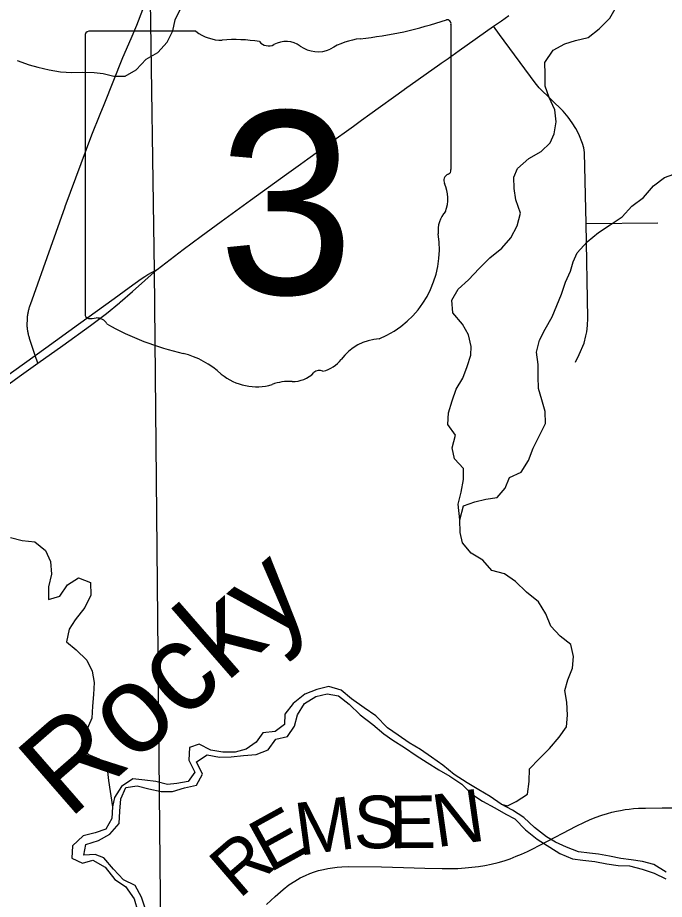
# Model space of a CAD drawing. Extents: x 0 to 34, y 0 to 22.
# Drawn here: x 6.6481 to 6.9977, y 17.3987 to 17.8754 of the extents above; entities that cross this region are included whole.
import ezdxf

# ---------------------------------------------------------------- set-up
doc = ezdxf.new("R2010")
doc.units = 0
for name, color, linetype in [('GM_X_County_Road', 7, 'Continuous'), ('GM_X_County_Road_Text', 7, 'Continuous'), ('GM_X_Minor_River', 7, 'Continuous'), ('GM_X_Minor_River_Text', 7, 'Continuous'), ('GM_X_Rail_Line_Text', 7, 'Continuous'), ('GM_X_State_Location', 7, 'Continuous'), ('GM_X_State_Route', 7, 'Continuous'), ('GM_X_State_Shield', 7, 'Continuous'), ('GM_X_Township', 7, 'Continuous'), ('GM_X_Township_Road', 7, 'Continuous')]:
    doc.layers.add(name, color=color, linetype=linetype)

msp = doc.modelspace()

# ---------------------------------------------------------------- linework, layer by layer
at = {"layer": 'GM_X_County_Road'}
for points in [[(6.659023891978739, 17.68859297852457), (6.657610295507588, 17.69283072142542), (6.654935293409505, 17.700846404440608), (6.654733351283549, 17.701418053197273), (6.654578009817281, 17.701887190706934), (6.654428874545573, 17.702359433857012), (6.654292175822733, 17.702834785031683), (6.654161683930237, 17.703310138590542), (6.654037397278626, 17.70379170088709), (6.653922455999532, 17.70427326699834), (6.653816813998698, 17.704754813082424), (6.653720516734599, 17.705239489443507), (6.65363351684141, 17.705727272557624), (6.653552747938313, 17.706215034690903), (6.653481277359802, 17.70670282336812), (6.653416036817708, 17.70719369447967), (6.653363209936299, 17.707684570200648), (6.653316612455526, 17.708178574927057), (6.653279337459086, 17.708672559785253), (6.6533507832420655, 17.71305942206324), (6.65340049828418, 17.71355962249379), (6.653459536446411, 17.71405672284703), (6.653527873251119, 17.714553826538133), (6.653605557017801, 17.715047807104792), (6.653692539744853, 17.715541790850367), (6.653785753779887, 17.716032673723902), (6.653888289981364, 17.716523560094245), (6.654000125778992, 17.717011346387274), (6.654121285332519, 17.717496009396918), (6.6542486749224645, 17.717980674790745), (6.654385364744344, 17.718462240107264), (6.654531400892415, 17.718940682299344), (6.654683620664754, 17.719419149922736), (6.654845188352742, 17.71989139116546), (6.655016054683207, 17.720363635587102), (6.666032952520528, 17.75132339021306), (6.6737876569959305, 17.773114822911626), (6.673828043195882, 17.773226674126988), (6.688278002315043, 17.812068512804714), (6.692680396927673, 17.823153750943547), (6.694780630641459, 17.828444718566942), (6.704896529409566, 17.853920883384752), (6.709392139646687, 17.8640243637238), (6.712558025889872, 17.87132234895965), (6.71577050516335, 17.87972016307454)], [(6.782536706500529, 17.3958811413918), (6.787274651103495, 17.400373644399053), (6.791562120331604, 17.40412360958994), (6.794774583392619, 17.40651278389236), (6.797865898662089, 17.40857572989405), (6.80083295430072, 17.41030623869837), (6.8037161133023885, 17.411707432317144), (6.806108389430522, 17.41269539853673), (6.8086218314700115, 17.41360260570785), (6.810805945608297, 17.414301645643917), (6.813359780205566, 17.41496029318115), (6.815708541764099, 17.415457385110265), (6.818221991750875, 17.415827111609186), (6.820735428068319, 17.416116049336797), (6.823332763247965, 17.416321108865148), (6.827123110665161, 17.416445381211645), (6.844760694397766, 17.416280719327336), (6.856709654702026, 17.41599177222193), (6.868208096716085, 17.415538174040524), (6.877643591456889, 17.4153735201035), (6.886050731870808, 17.415497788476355), (6.8899653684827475, 17.41574322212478), (6.893591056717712, 17.416072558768), (6.897300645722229, 17.416526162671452), (6.900597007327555, 17.41702325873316), (6.904098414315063, 17.417722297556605), (6.9077676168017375, 17.418629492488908), (6.911104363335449, 17.419577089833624), (6.914319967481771, 17.42068934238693), (6.917656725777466, 17.422006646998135), (6.92049949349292, 17.42324315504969), (6.923618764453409, 17.42465368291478), (6.92664172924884, 17.426113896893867), (6.929962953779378, 17.4278071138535), (6.934592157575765, 17.43016833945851), (6.9427942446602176, 17.43461733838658), (6.950045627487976, 17.438367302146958), (6.954497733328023, 17.44054831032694), (6.957154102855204, 17.441750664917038), (6.960319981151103, 17.442987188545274), (6.963858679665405, 17.44425788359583), (6.966859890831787, 17.445208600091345), (6.96932983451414, 17.44586724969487), (6.971802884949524, 17.44644511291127), (6.973987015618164, 17.446855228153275), (6.976460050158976, 17.447268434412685), (6.978684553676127, 17.44755736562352), (6.981073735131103, 17.447802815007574), (6.983711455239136, 17.448010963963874), (6.987545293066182, 17.448091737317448), (6.996527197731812, 17.448175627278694), (7.005387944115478, 17.448216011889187)]]:
    msp.add_lwpolyline(points, dxfattribs=at)
at = {"layer": 'GM_X_Minor_River'}
for points in [[(6.647802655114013, 17.852279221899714), (6.654275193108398, 17.8499260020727), (6.659026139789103, 17.848680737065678), (6.665106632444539, 17.847079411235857), (6.671176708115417, 17.846048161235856), (6.677422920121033, 17.845778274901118), (6.683095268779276, 17.845876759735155), (6.689527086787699, 17.84580005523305), (6.694267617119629, 17.845123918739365), (6.700155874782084, 17.84370914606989), (6.706206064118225, 17.843814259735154), (6.712199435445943, 17.847144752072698), (6.717582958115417, 17.85293073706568), (6.7239513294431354, 17.85645630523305), (6.7289598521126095, 17.862046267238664), (6.732066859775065, 17.86817126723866), (6.733284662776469, 17.874263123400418), (6.7365734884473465, 17.880770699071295)], [(6.887083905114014, 17.603966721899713), (6.8861804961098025, 17.612298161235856), (6.887769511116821, 17.61877448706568), (6.889160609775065, 17.625628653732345), (6.889054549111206, 17.63169778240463), (6.884233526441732, 17.636924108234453), (6.882995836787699, 17.64278395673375), (6.884765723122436, 17.649643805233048), (6.880691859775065, 17.655452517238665), (6.88095985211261, 17.661717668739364), (6.882926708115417, 17.668201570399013), (6.885083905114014, 17.67449986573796), (6.8887628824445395, 17.680444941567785), (6.8911104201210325, 17.686746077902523), (6.893082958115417, 17.69285024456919), (6.893189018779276, 17.697595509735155), (6.89175530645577, 17.703830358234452), (6.888626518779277, 17.70965611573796), (6.883410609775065, 17.71582467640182), (6.882723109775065, 17.722641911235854), (6.886212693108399, 17.72858509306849), (6.891797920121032, 17.733614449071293), (6.897552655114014, 17.739784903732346), (6.90331307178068, 17.74557751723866), (6.909840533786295, 17.750814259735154), (6.914660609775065, 17.75639948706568), (6.918138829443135, 17.762909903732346), (6.919909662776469, 17.769770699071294), (6.917324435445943, 17.77693452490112), (6.9164607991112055, 17.782989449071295), (6.916354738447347, 17.78905952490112), (6.918350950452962, 17.793836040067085), (6.924496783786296, 17.799255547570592), (6.931050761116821, 17.80297524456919), (6.935886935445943, 17.80761255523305), (6.938068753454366, 17.812583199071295), (6.939278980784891, 17.819053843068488), (6.938408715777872, 17.825489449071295), (6.935453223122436, 17.832266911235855), (6.933265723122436, 17.83830005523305), (6.933341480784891, 17.844751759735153), (6.933039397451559, 17.851196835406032), (6.9376520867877, 17.857727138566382), (6.943832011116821, 17.861250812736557), (6.949663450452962, 17.863060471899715), (6.95644280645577, 17.86469588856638), (6.962413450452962, 17.869353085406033), (6.968174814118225, 17.875145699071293), (6.971846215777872, 17.881470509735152)], [(6.887083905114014, 17.603966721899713), (6.889033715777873, 17.611398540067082), (6.895236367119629, 17.61359456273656), (6.90126288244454, 17.615028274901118), (6.907300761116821, 17.615891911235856), (6.911559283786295, 17.621088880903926), (6.913917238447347, 17.62682088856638), (6.920298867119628, 17.62958793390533), (6.924158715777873, 17.635915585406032), (6.9266890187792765, 17.642598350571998), (6.9301615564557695, 17.649489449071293), (6.933450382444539, 17.655996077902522), (6.933337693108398, 17.662443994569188), (6.9315223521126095, 17.668862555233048), (6.929713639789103, 17.67490043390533), (6.929410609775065, 17.681345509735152), (6.929486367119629, 17.687796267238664), (6.928609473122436, 17.69460971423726), (6.93019754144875, 17.70108793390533), (6.933308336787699, 17.707023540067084), (6.936973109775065, 17.71372713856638), (6.94205360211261, 17.725956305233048), (6.944208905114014, 17.732443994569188), (6.946941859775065, 17.738372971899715), (6.948367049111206, 17.743330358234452), (6.950548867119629, 17.74830005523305), (6.95592860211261, 17.75427543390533), (6.962081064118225, 17.75931520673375), (6.968439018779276, 17.763410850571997), (6.974795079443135, 17.767694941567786), (6.980177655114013, 17.77348092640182), (6.986337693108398, 17.77814096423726), (6.991899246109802, 17.784498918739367), (6.997684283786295, 17.788963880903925), (7.0027590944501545, 17.790759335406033)], [(6.909466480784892, 17.450140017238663), (6.912872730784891, 17.449371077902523), (6.917574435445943, 17.45160971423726), (6.9237429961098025, 17.455700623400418), (6.924567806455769, 17.462544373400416), (6.924825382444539, 17.46937770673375), (6.930026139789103, 17.474780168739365), (6.9356018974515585, 17.480378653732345), (6.940792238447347, 17.486349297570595), (6.944854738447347, 17.49192221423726), (6.945307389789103, 17.498379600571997), (6.944994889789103, 17.505391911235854), (6.943939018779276, 17.51163338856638), (6.945541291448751, 17.51735213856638), (6.948077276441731, 17.52365611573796), (6.948530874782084, 17.530113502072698), (6.947093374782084, 17.536538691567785), (6.941341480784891, 17.54099039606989), (6.936329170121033, 17.54640327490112), (6.933561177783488, 17.553183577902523), (6.929666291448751, 17.55956520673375), (6.923143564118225, 17.56476217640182), (6.917178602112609, 17.57053774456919), (6.9112411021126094, 17.574798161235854), (6.9044001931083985, 17.57657467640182), (6.899573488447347, 17.58218073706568), (6.893266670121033, 17.585864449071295), (6.888628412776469, 17.591474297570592), (6.887393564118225, 17.59714380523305), (6.887083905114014, 17.603966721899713)], [(6.644214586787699, 17.594405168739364), (6.650484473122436, 17.592807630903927), (6.657307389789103, 17.591978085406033), (6.663064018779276, 17.58733698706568), (6.665816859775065, 17.58131520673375), (6.666315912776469, 17.57449418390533), (6.6647344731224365, 17.56763717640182), (6.664855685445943, 17.560810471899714), (6.67087557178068, 17.562623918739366), (6.675117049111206, 17.568766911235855), (6.680915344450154, 17.572473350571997), (6.687386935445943, 17.570121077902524), (6.68770038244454, 17.56310782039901), (6.684409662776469, 17.55660024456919), (6.679233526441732, 17.549870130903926), (6.67591629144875, 17.544880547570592), (6.674524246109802, 17.538027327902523), (6.67970985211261, 17.533564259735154), (6.685482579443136, 17.527975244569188), (6.688421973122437, 17.522145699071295), (6.689477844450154, 17.515904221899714), (6.689024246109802, 17.50944683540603), (6.688566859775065, 17.503178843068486), (6.688113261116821, 17.49672145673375), (6.685212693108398, 17.489651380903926), (6.682496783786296, 17.48277543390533), (6.6860005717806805, 17.477145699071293), (6.691905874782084, 17.474783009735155), (6.6965375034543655, 17.469552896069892), (6.697221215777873, 17.4629260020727), (6.6993632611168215, 17.448735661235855)], [(6.99863030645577, 17.413384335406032), (6.991936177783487, 17.417630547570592), (6.985854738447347, 17.41923092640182), (6.979787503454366, 17.420072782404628), (6.97409905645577, 17.420921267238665), (6.9680251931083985, 17.42214285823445), (6.962143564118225, 17.42317789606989), (6.957217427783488, 17.423660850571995), (6.951338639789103, 17.42450649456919), (6.944864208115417, 17.427049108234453), (6.938766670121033, 17.429597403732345), (6.933986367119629, 17.43254910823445), (6.927467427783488, 17.43755573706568), (6.921697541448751, 17.442956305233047), (6.915573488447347, 17.447022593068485), (6.909466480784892, 17.450140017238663), (6.903528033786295, 17.454398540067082), (6.897414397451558, 17.457895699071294), (6.891104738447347, 17.46176880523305), (6.884028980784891, 17.46619683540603), (6.877887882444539, 17.471211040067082), (6.871757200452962, 17.475656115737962), (6.865821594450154, 17.479725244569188), (6.859705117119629, 17.483411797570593), (6.8537695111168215, 17.487481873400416), (6.8480232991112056, 17.491554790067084), (6.841671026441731, 17.49789285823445), (6.835350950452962, 17.50233414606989), (6.828646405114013, 17.50714948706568), (6.822890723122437, 17.511790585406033), (6.816235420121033, 17.513761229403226), (6.809833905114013, 17.51213149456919), (6.803256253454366, 17.509739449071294), (6.797104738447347, 17.504700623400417), (6.792477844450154, 17.49892789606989), (6.792388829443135, 17.493235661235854), (6.787347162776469, 17.489544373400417), (6.780549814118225, 17.488854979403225), (6.777047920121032, 17.483673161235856), (6.771629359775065, 17.479973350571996), (6.7656047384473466, 17.47835024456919), (6.758987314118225, 17.478233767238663), (6.752535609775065, 17.47944967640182), (6.746239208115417, 17.482564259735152), (6.740975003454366, 17.480765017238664), (6.740717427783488, 17.47393073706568), (6.7438566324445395, 17.467535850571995), (6.740350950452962, 17.46254342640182), (6.734131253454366, 17.461296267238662), (6.72903182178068, 17.460826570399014), (6.722762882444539, 17.462425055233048), (6.716885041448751, 17.463269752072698), (6.710442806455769, 17.46391558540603), (6.704274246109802, 17.45982467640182), (6.70040682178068, 17.453876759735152), (6.6993632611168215, 17.448735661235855), (6.699095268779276, 17.44247145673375), (6.695792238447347, 17.436722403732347), (6.689963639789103, 17.434723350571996), (6.6835621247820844, 17.433094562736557), (6.677794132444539, 17.42768168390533), (6.67734432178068, 17.42103395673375), (6.683066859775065, 17.41828963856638), (6.688712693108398, 17.419906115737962), (6.695396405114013, 17.41622903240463), (6.700621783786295, 17.40949229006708), (6.706365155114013, 17.405609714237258), (6.711019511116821, 17.3990510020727), (6.713030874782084, 17.392257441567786)], [(6.717170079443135, 17.393467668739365), (6.7149768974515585, 17.399879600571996), (6.711649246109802, 17.406270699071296), (6.705351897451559, 17.409385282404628), (6.699957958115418, 17.414981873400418), (6.6947420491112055, 17.42114948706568), (6.689981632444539, 17.42296293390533), (6.683935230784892, 17.422667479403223), (6.68496932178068, 17.428376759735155), (6.6917392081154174, 17.430581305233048), (6.697921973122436, 17.43391558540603), (6.702926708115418, 17.439693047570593), (6.703376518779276, 17.446340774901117), (6.703823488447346, 17.453176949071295), (6.706552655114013, 17.45929532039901), (6.712778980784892, 17.46016274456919), (6.7190488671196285, 17.458566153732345), (6.725696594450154, 17.456974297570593), (6.731746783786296, 17.457080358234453), (6.738331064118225, 17.459092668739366), (6.7447363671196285, 17.46053395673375), (6.748035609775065, 17.46647145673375), (6.744704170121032, 17.47305289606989), (6.7504986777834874, 17.476946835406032), (6.757143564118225, 17.475546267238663), (6.76356780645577, 17.475848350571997), (6.770176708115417, 17.476533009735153), (6.776975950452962, 17.47703206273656), (6.783549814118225, 17.479612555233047), (6.787610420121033, 17.48537486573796), (6.794014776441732, 17.48681520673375), (6.797700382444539, 17.492380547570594), (6.7992941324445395, 17.498479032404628), (6.803158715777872, 17.504616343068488), (6.809333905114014, 17.50832846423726), (6.815361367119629, 17.50976217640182), (6.821620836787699, 17.50873282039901), (6.827373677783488, 17.50428111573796), (6.8333376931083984, 17.49850554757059), (6.840049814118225, 17.49331236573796), (6.846001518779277, 17.488294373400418), (6.850980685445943, 17.484777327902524), (6.8572903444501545, 17.480904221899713), (6.863609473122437, 17.47646198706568), (6.869538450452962, 17.472772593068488), (6.875850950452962, 17.468710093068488), (6.88177235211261, 17.465399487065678), (6.888282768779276, 17.460960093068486), (6.893672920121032, 17.455553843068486), (6.899412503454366, 17.451860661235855), (6.906097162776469, 17.448183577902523), (6.912018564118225, 17.444872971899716), (6.916792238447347, 17.4423010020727), (6.9225715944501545, 17.4363322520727), (6.928901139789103, 17.43132183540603), (6.941142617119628, 17.423568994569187), (6.948003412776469, 17.420654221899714), (6.953688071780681, 17.419995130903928), (6.960133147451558, 17.419159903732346), (6.966585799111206, 17.41794399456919), (6.972653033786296, 17.41710213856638), (6.978899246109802, 17.416832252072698), (6.985739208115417, 17.41505573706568), (6.992208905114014, 17.412891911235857), (6.998504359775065, 17.409778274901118)]]:
    msp.add_lwpolyline(points, dxfattribs=at)
at = {"layer": 'GM_X_Rail_Line_Text'}
msp.add_lwpolyline([(7.255462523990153, 17.906184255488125), (6.967662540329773, 17.900846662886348), (6.9468000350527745, 17.9005173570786), (6.719611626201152, 17.89693202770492), (6.721941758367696, 17.738473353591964), (6.725763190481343, 17.34372005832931), (6.731116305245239, 16.7724510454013), (6.731100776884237, 16.538635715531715), (6.731114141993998, 16.53753691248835), (6.731609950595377, 16.496752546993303), (6.731638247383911, 16.49442522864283), (6.731696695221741, 16.480747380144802), (6.732387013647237, 16.319149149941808), (6.74000812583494, 15.641470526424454), (6.982830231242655, 15.643260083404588), (6.999225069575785, 15.643974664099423)], dxfattribs=at)
at = {"layer": 'GM_X_State_Route'}
for points in [[(6.880834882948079, 17.85337380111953), (6.8816669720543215, 17.853948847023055), (6.88282270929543, 17.854762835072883), (6.886787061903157, 17.857559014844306), (6.905235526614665, 17.870815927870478), (6.909609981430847, 17.87365558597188), (6.913591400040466, 17.876509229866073)], [(6.723546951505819, 17.739265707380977), (6.737530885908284, 17.750105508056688), (6.7472491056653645, 17.75732581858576), (6.758026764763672, 17.765155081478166), (6.774033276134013, 17.776780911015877), (6.793398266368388, 17.790715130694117), (6.801044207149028, 17.796217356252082), (6.804878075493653, 17.798976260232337), (6.816426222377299, 17.80728707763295), (6.829558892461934, 17.816738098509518), (6.834004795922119, 17.81993817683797), (6.83853767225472, 17.82320036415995), (6.857104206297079, 17.836559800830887), (6.857194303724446, 17.836625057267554), (6.87637912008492, 17.850292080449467), (6.877090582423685, 17.85078608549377), (6.880834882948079, 17.85337380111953)], [(6.597008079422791, 17.649325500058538), (6.604219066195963, 17.654560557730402), (6.626641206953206, 17.670514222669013), (6.640308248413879, 17.680362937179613), (6.657610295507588, 17.69283072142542), (6.663264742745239, 17.696903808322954), (6.680967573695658, 17.70968229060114), (6.7003294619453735, 17.723569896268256), (6.708351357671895, 17.72954436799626), (6.71488194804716, 17.734210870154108), (6.716861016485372, 17.73544116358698), (6.718541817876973, 17.736491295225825), (6.720875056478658, 17.73777752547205), (6.723546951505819, 17.739265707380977)], [(6.703576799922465, 17.721625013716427), (6.7101377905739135, 17.72738199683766), (6.723546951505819, 17.739265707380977)], [(6.599822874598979, 17.646013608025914), (6.606263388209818, 17.65050922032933), (6.615372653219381, 17.657126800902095), (6.6283499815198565, 17.666565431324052), (6.637838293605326, 17.673465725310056), (6.648845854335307, 17.68146898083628), (6.659023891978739, 17.68859297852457), (6.672454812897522, 17.698087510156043), (6.687529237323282, 17.7089677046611), (6.696048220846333, 17.715389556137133), (6.703190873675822, 17.72128637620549), (6.703576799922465, 17.721625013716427)]]:
    msp.add_lwpolyline(points, dxfattribs=at)
at = {"layer": 'GM_X_State_Shield'}
for p, q in [((6.882352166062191, 17.793211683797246), (6.882352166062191, 17.87172573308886)), ((6.68460237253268, 17.86542379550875), (6.68460237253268, 17.715333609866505)), ((6.744461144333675, 17.86800624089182), (6.686548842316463, 17.86800624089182)), ((6.882332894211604, 17.79323095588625), (6.882352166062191, 17.793211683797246))]:
    msp.add_line(p, q, dxfattribs=at)
for centre, radius, start, end in [((6.811910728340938, 18.07263036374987), 0.20971181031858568, 275.8444694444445, 288.9064527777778), ((6.880158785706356, 17.87205135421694), 0.0022014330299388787, 351.8620861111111, 97.738), ((6.686867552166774, 17.865743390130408), 0.0022909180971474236, 98.1301027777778, 188.13010277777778), ((6.758252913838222, 17.885430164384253), 0.02222066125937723, 231.61950555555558, 271.11188333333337), ((6.765620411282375, 17.783743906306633), 0.07977191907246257, 80.48669166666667, 94.98826944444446), ((6.783730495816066, 17.866521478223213), 0.006410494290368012, 219.79206111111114, 297.1023694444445), ((6.793141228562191, 17.849173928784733), 0.013327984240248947, 54.466683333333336, 119.14113055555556), ((6.810343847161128, 17.872967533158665), 0.01603338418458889, 233.85620555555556, 294.82819166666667), ((6.83866003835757, 17.822164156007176), 0.04219079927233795, 97.34618055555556, 120.7688527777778), ((6.880003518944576, 17.79290832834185), 0.0023559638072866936, 289.6038111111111, 7.734130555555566), ((6.88184359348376, 17.787447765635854), 0.0034068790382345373, 107.94398333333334, 210.33696666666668), ((6.860169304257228, 17.777523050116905), 0.02045151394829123, 340.0329638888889, 23.649566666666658), ((6.890239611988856, 17.76035450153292), 0.014879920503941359, 136.80649722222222, 186.92959444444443), ((6.823658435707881, 17.75036647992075), 0.05245371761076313, 292.3088861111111, 8.985838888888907), ((6.686888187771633, 17.715005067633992), 0.002311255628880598, 171.9583861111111, 258.30661388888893), ((6.687238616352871, 17.73036051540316), 0.017637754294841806, 267.33899444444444, 280.6038555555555), ((6.690847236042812, 17.706674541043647), 0.006359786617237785, 29.748380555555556, 93.27174722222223), ((6.771142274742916, 17.841524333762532), 0.15144107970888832, 240.41292222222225, 257.1985), ((6.845775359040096, 17.673196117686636), 0.02872754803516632, 94.40312222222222, 142.57675), ((6.72599232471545, 17.64790508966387), 0.047382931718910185, 47.184155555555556, 75.83597222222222), ((6.809377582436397, 17.70078689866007), 0.016946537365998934, 282.8731916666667, 323.27711111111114), ((6.796809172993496, 17.694690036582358), 0.016019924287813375, 268.7770194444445, 315.54927222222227), ((6.811300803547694, 17.680153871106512), 0.004510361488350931, 65.75173055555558, 132.64842222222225), ((6.777239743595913, 17.705929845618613), 0.030067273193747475, 230.70037222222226, 286.29183611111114), ((6.794612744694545, 17.65403764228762), 0.024705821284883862, 85.69512222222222, 111.20994722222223)]:
    msp.add_arc(centre, radius, start, end, dxfattribs=at)
at = {"layer": 'GM_X_Township'}
msp.add_lwpolyline([(4.294165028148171, 16.81302957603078), (4.292581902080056, 17.167391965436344), (4.2913906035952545, 17.310082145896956), (4.289693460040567, 17.5127793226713), (4.287983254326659, 17.717367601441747), (4.286780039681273, 17.83810687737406), (4.286849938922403, 17.8401123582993), (4.2869198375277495, 17.842117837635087), (4.289871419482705, 17.842195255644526), (4.756740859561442, 17.85444271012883), (5.239619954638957, 17.864894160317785), (5.687863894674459, 17.874599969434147), (6.142964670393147, 17.884451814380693), (6.517767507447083, 17.892563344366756), (6.521664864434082, 17.892647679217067), (6.526862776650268, 17.892760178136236), (6.719611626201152, 17.89693202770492), (6.721941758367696, 17.738473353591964), (6.725763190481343, 17.34372005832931), (6.731116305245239, 16.7724510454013)], dxfattribs=at)
at = {"layer": 'GM_X_Township_Road'}
msp.add_line((6.955470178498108, 17.764070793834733), (6.994097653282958, 17.76446846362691), dxfattribs=at)
msp.add_lwpolyline([(6.949588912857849, 17.68911803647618), (6.951654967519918, 17.693330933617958), (6.95427714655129, 17.699451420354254), (6.955311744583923, 17.703347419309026), (6.95570942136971, 17.705491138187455), (6.9561070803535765, 17.7089894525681), (6.956343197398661, 17.712963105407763), (6.955470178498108, 17.764070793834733), (6.954435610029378, 17.80253980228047), (6.954118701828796, 17.805003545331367), (6.953481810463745, 17.807308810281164), (6.951415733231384, 17.812475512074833), (6.9497504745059, 17.815498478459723), (6.94791742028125, 17.818437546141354), (6.94577369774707, 17.821538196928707), (6.9429899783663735, 17.824797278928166), (6.92995672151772, 17.83743284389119), (6.927809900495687, 17.840135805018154), (6.9086530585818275, 17.866286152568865), (6.905235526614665, 17.870815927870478)], dxfattribs=at)

# ---------------------------------------------------------------- texts
at = {"layer": 'GM_X_County_Road_Text'}
for s, height, rotation, p in [('S', 0.02840909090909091, 0.09977699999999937, (6.829761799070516, 17.42635323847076)), ('E', 0.02840909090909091, 0.309697, (6.849042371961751, 17.426388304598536)), ('N', 0.028409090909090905, 8.105026, (6.874498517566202, 17.42681130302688)), ('M', 0.028409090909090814, 7.675640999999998, (6.800194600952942, 17.42230224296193)), ('E', 0.02840909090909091, 28.894342, (6.7842159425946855, 17.41290201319)), ('R', 0.028409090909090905, 40.707127, (6.76779775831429, 17.398566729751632))]:
    msp.add_text(s, height=height, rotation=rotation, dxfattribs=at).set_placement(p)
at = {"layer": 'GM_X_Minor_River_Text'}
msp.add_text('Rocky', height=0.047366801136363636, rotation=41.07333055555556, dxfattribs=at).set_placement((6.675781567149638, 17.441587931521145))
at = {"layer": 'GM_X_State_Location'}
for s, p in [('s', (6.78204375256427, 17.762239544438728)), ('r', (6.7820388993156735, 17.762239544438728))]:
    msp.add_text(s, height=9.46969696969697e-05, dxfattribs=at).set_placement(p)
msp.add_text('3', height=9.46969696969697e-05, rotation=1e-05, dxfattribs=at).set_placement((6.767780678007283, 17.755349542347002))
at = {"layer": 'GM_X_State_Shield'}
msp.add_text('3', height=0.09887715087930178, dxfattribs=at).set_placement((6.75640931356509, 17.72591753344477))

doc.saveas('drawing.dxf')
